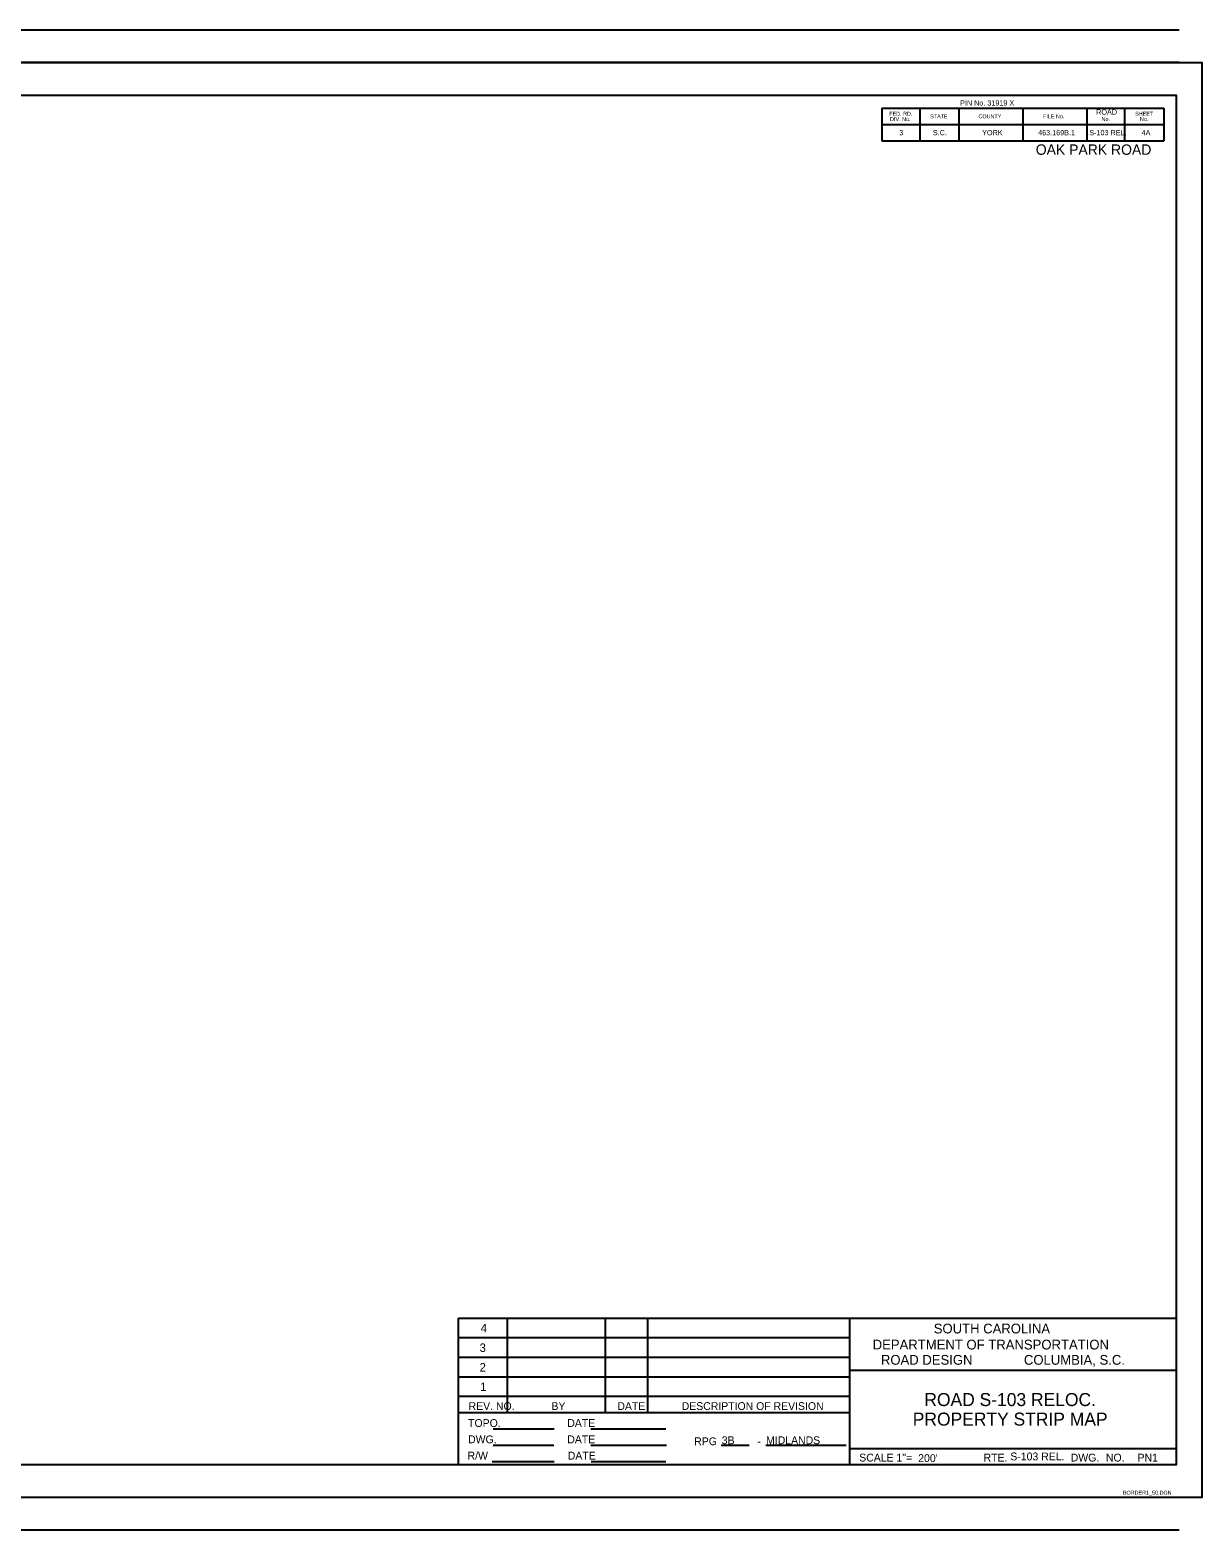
# Model space of a CAD drawing. Extents: x -189 to 1607, y -50 to 1100.
# Drawn here: x 709 to 1607, y -50 to 1100 of the extents above; entities that cross this region are included whole.
import ezdxf

# ---------------------------------------------------------------- set-up
doc = ezdxf.new("R2010")
doc.units = 0
for name, color, linetype in [('RD_SHT_Bndy', 7, 'Continuous'), ('RD_SHT_IplotShp', 7, 'Continuous'), ('RD_SHT_TX', 7, 'Continuous')]:
    doc.layers.add(name, color=color, linetype=linetype)

msp = doc.modelspace()

# ---------------------------------------------------------------- linework, layer by layer
at = {"layer": 'RD_SHT_Bndy'}
for p, q in [((1589.9, 1100), (-170.1, 1100)), ((1589.9, 1075), (-170.1, 1075)), ((1362, 1040), (1362, 1015)), ((1362, 1040), (1519, 1040)), ((1391, 1040), (1391, 1015)), ((1421, 1040), (1421, 1015)), ((1470, 1040), (1470, 1015)), ((1519, 1040), (1519, 1015)), ((1519, 1040), (1578, 1040)), ((1548, 1040), (1548, 1015)), ((1578, 1040), (1578, 1015)), ((1362, 1027.5), (1519, 1027.5)), ((1519, 1027.5), (1578, 1027.5)), ((1362, 1015), (1519, 1015)), ((1519, 1015), (1578, 1015)), ((1037.5, 0), (1037.5, 112.5)), ((1037.5, 112.5), (1587.5, 112.5)), ((1075, 39.9), (1075, 112.5)), ((1150, 39.9), (1150, 112.5)), ((1182.5, 39.9), (1182.5, 112.5)), ((1337.5, 0), (1337.5, 112.5)), ((1037.5, 97.5), (1337.5, 97.5)), ((1037.5, 82.5), (1337.5, 82.5)), ((1337.5, 72.5), (1587.5, 72.5)), ((1037.5, 67.5), (1337.5, 67.5)), ((1037.5, 52.5), (1337.5, 52.5)), ((1037.5, 40), (1337.5, 40)), ((1064, 27.5), (1110.8, 27.5)), ((1138.8, 27.5), (1196.4, 27.5)), ((1064, 15), (1110.4, 15)), ((1138.8, 15), (1196.8, 15)), ((1238.7, 15), (1260.1, 15)), ((1273, 15), (1334.6, 15)), ((1337.5, 12.5), (1587.5, 12.5)), ((1063.2, 2.5), (1110.8, 2.5)), ((1139.2, 2.5), (1196.4, 2.5)), ((1589.9, -25), (-170.1, -25)), ((1589.9, -50), (-170.1, -50))]:
    msp.add_line(p, q, dxfattribs=at)
msp.add_lwpolyline([(-87.5, 1050), (1587.5, 1050), (1587.5, 0), (-87.5, 0)], close=True, dxfattribs=at)
at = {"layer": 'RD_SHT_IplotShp'}
msp.add_lwpolyline([(-188.7, 1075), (1607.3, 1075), (1607.3, -25), (-188.7, -25)], close=True, dxfattribs=at)

# ---------------------------------------------------------------- texts
at = {"layer": 'RD_SHT_TX'}
for s, height, p in [('FED. RD.', 3, (1367.6, 1034.3)), ('STATE', 3, (1399, 1032.3)), ('PIN No. 31919 X   ', 4, (1421.9, 1042.1)), ('COUNTY', 3, (1436, 1032.3)), ('FILE No.', 3, (1485.5, 1032.3)), ('      ROAD      ', 4, (1517, 1035.1)), ('SHEET', 3, (1556.1, 1034.3)), ('DIV. No.', 3, (1368.2, 1030.2)), ('No.', 3, (1530.3, 1030.2)), ('No.', 3, (1559.8, 1030.2)), ('3', 4, (1375.3, 1019.3)), ('S.C.', 4, (1401, 1019.3)), ('      YORK      ', 4, (1429.6, 1019.3)), ('OAK PARK ROAD', 8, (1479.9, 1004.3)), ('   463.169B.1  ', 4, (1477.1, 1019.3)), ('   S-103 REL.   ', 4, (1516.3, 1019.3)), ('       4A       ', 4, (1550.3, 1019.3)), ('4', 6.5, (1054.4, 101.5)), ('SOUTH CAROLINA', 7.5, (1401.7, 100.7)), ('3', 6.5, (1053.6, 86.5)), ('DEPARTMENT OF TRANSPORTATION', 7.5, (1354.9, 88.4)), ('ROAD DESIGN', 7.5, (1361.2, 76.7)), ('COLUMBIA, S.C.', 7.5, (1470.8, 76.7)), ('2', 6.5, (1053.6, 71.5)), ('1', 6.5, (1054, 56.5)), ('REV. NO.', 6, (1045.2, 42)), ('BY', 6, (1108.7, 42)), ('DATE', 6, (1159.2, 42)), ('DESCRIPTION OF REVISION', 6, (1208.5, 42)), ('ROAD S-103 RELOC.', 10, (1394.5, 45)), ('TOPO.', 6, (1044.8, 29)), ('DATE', 6, (1120.8, 29)), ('PROPERTY STRIP MAP', 10, (1385.6, 30)), ('DWG.', 6, (1044.8, 16.5)), ('DATE', 6, (1120.8, 16.5)), ('RPG', 6, (1218.1, 15)), ('3B    ', 6, (1239.2, 15.8)), ('-', 6, (1266.4, 15)), ('MIDLANDS  ', 6, (1273.2, 15.8)), ('R/W', 6, (1044.4, 4)), ('DATE', 6, (1121.2, 4)), ('SCALE 1"=', 6, (1344.6, 2.5)), ("200' ", 6, (1389.8, 2.1)), ('RTE.', 6, (1439.9, 2.5)), ('S-103 REL. ', 6, (1460.4, 3.4)), ('DWG.', 6, (1506.7, 2.5)), ('NO.', 6, (1533.7, 2.5)), ('PN1', 6, (1557.9, 2.5)), ('BORDER1_50.DGN', 3, (1546.7, -22.9))]:
    msp.add_text(s, height=height, dxfattribs=at).set_placement(p)

doc.saveas('drawing.dxf')
